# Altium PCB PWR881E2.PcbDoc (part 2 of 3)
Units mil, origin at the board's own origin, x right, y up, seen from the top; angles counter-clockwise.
Board outline 6500 x 3500 mil, 6 copper layers (Top Layer, Signal Layer 1, Signal Layer 2, Signal Layer 3, Signal Layer 4, Bottom Layer), stack 32.4 mil thick; 330 components, 152 nets, 836 pads, 570 vias.
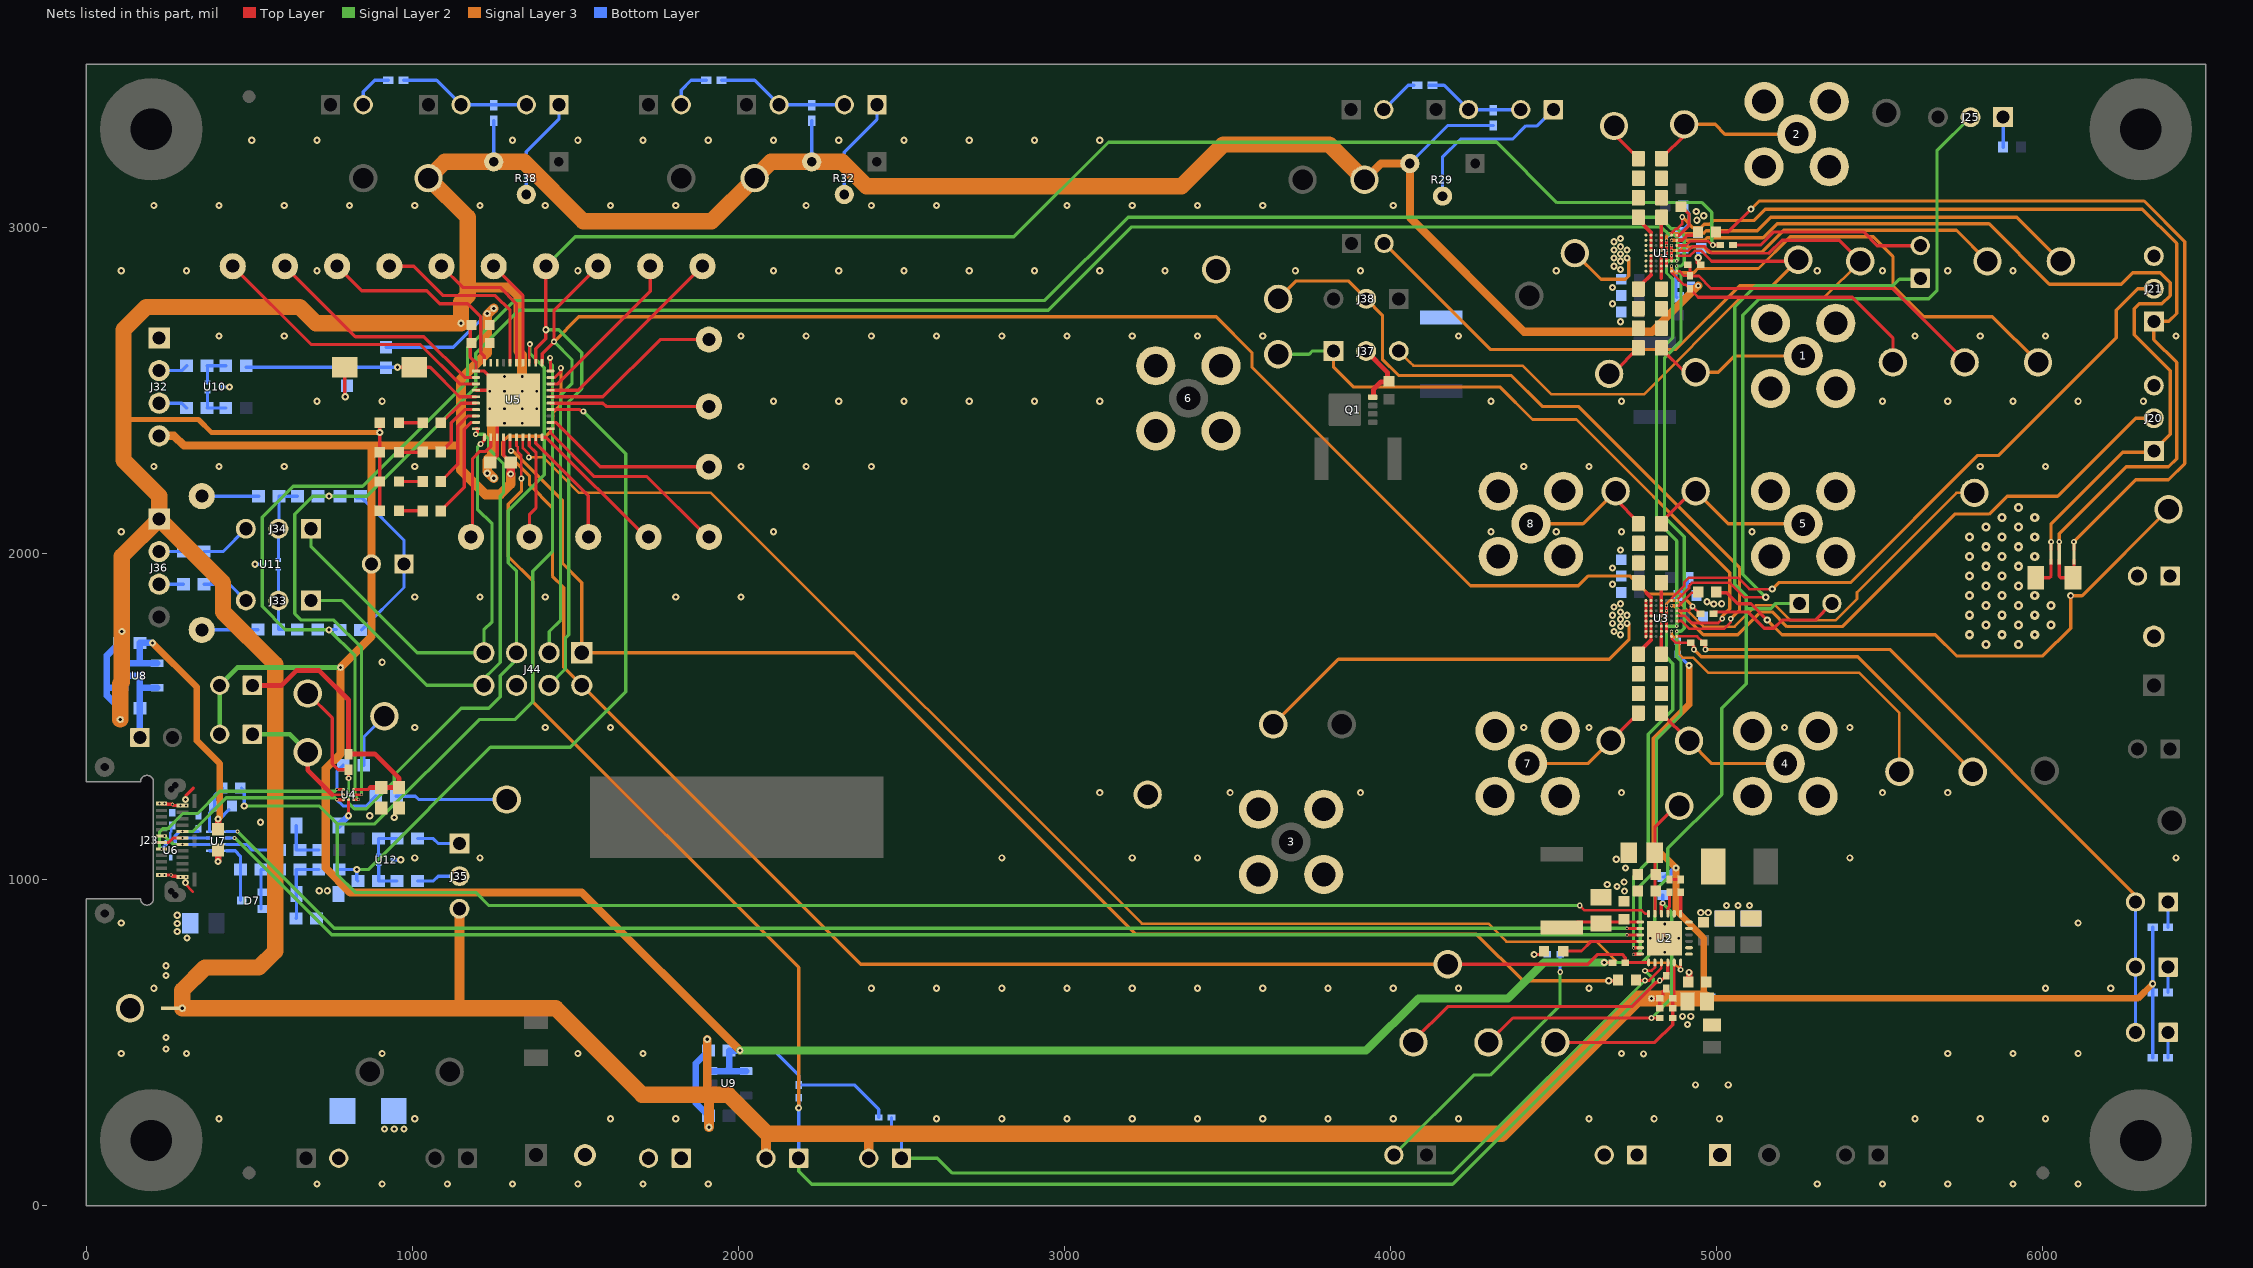
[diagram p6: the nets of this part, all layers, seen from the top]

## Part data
1 2 3 4 5 6 7 8: library part TP_PROBE, "Adaptor, 3.5-mm probe clip (or 131-5031-00)"
C1: "CAP, CERM, 1 µF, 25 V, +/- 10%, X7R, 0805"
C2 C4: "CAP, CERM, 10 µF, 25 V, +/- 20%, X5R, 0603"
C3: "CAP, CERM, 1000 pF, 25 V, +/- 5%, C0G/NP0, 0603"
C5 C29: "CAP, CERM, 1 µF, 25 V, +/- 10%, X5R, 0603"
C6 C28: "CAP, CERM, 0.22 µF, 16 V, +/- 10%, X7R, 0402"
C7 C30 C45 C57 C58: "CAP, CERM, 10 µF, 10 V, +/- 20%, X7T, 0603"
C8 C31: "CAP, CERM, 4.7 µF, 10 V, +/- 20%, X5R, 0402"
C9: "CAP, CERM, 22 µF, 25 V, +/- 20%, X5R, 0805"
C10 C18 C22 C25 C26: "CAP, CERM, 10 µF, 10 V, +/- 10%, X7R, 0805"
C11: "CAP, CERM, 0.047 µF, 25 V, +/- 10%, X7R, 0402"
C12: "CAP, CERM, 1 µF, 16 V, +/- 10%, X7R, 0603"
C13 C14 C16 C17 C20 C21 C23 C24 C33 C34 C36 C37 C38 C39 C40 C41: "CAP, CERM, 20 µF, 16 V, +/- 20%, X5R, 0704"
C15 C35 C53 C54 C55 C56: "CAP, CERM, 22 µF, 10 V, +/- 20%, X5R, 0603"
C19 C51 C52: "CAP, CERM, 4.7 µF, 16 V, +/- 10%, X5R, 0603"
C27 C42 C43 C44 C46 C47: "CAP, CERM, 0.1 µF, 25 V, +/- 10%, X7R, 0603"
C32: "CAP, CERM, 10 µF, 25 V, +/- 10%, X5R, 0805"
C48: "CAP, CERM, 1000 pF, 25 V, +/- 10%, X7R, 0603"
C49 C50: "CAP, CERM, 1 µF, 25 V, +/- 10%, X7R, 0603"
C59 C60: "CAP, CERM, 270 pF, 50 V,+/- 10%, X7R, 0402"
C61: "CAP, CERM, 0.01 µF, 25 V,+/- 10%, X7R, 0603"
D1 D3 D4 D5 D6: "LED, Green, SMD"
D2: "Diode, TVS, Uni, 13 V, SMA"
D7: "Diode, Switching, 75 V, 0.15 A, SOT-323"
D8 D9: "Diode, Zener, 3.6 V, 500 mW, SOD-123"
D10: "Diode, TVS, Uni, 5 V, 19.6 Vc, SOD-323"
FID1 FID2 FID3 FID4 FID5 FID6: "Fiducial mark.  There is nothing to buy or mount."
H1 H3 H5 H7: "Standoff, Hex, 0.5\"L #4-40 Nylon"
H2 H4 H6 H8: "Machine Screw, Round, #4-40 x 1/4, Nylon, Philips panhead"
J1 J6 J8 J9: library part PEC02SAAN, "Header, 100mil, 2x1, Tin, TH"
J2 J3 J4 J7 J10 J12 J13 J14 J15 J16 J17 J18 J19 J22 J24 J26 J27 J29 J30 J31 J39 J40 J41 J42 J43: "Header, 100mil, 2x1, Tin, TH"
J5 J11 J28: "Conn Term Block, 2POS, 3.81mm, TH"
J20 J21 J25 J33 J34 J35 J37 J38: "Header, 2.54 mm, 3x1, Tin, TH"
J23: "Connector, Receptacle, USB Type C, R/A, SMT"
J32 J36: "Header (friction lock), 100mil, 4x1, R/A, TH"
J44: "Header(shrouded), 2.54mm, 4x2, Gold, TH"
L1: "Inductor, Shielded Drum Core, Powdered Iron, 1 µH, 7 A, 0.0181 ohm, SMD"
LBL1: library part THT-14-423-10, "Thermal Transfer Printable Labels, 0.650\" W x 0.200\" H - 10,000 per roll"
Logo1: library part TI_Logo, "Texas Instrument Corporate Signature"
Logo2: library part Pb-Free
Logo3: library part FCC_disclaimer, "FCC_disclaimer"
NT1 NT2 NT3 NT4 NT5 NT6 NT7: "Single point connection between nets."
Q1: "MOSFET, N-CH, 30 V, 60 A, DQG0008A (VSON-CLIP-8)"
R1 R4 R6 R7 R8 R19 R26 R27 R28 R30 R31 R34 R37: "RES, 10 k, 5%, 0.063 W, 0402"
R2: "RES, 2.21 k, 1%, 0.063 W, 0402"
R3: "RES, 18 k, 5%, 0.063 W, 0402"
R5 R10 R65 R66 R69 R70: "RES, 1.00 k, 1%, 0.1 W, 0603"
R9: "RES, 130, 1%, 0.063 W, 0402"
R11 R12 R20 R24: "RES, 0, 5%, 1.5 W, AEC-Q200 Grade 0, 2512"
R13: "RES, 0, 5%, 0.063 W, 0402"
R14: "RES, 0, 1%, 0.5 W, 0805"
R15 R16 R33 R35: "RES, 100, 5%, 0.1 W, 0603"
R17: "RES, 30.1 k, 1%, 0.063 W, 0402"
R18: "RES, 5.23 k, 1%, 0.063 W, 0402"
R21: "RES, 180 k, 5%, 0.063 W, 0402"
R22: "RES, 75 k, 5%, 0.063 W, 0402"
R23: "RES, 39 k, 5%, 0.063 W, 0402"
R25: "RES, 0.01, 1%, 1 W, 1206"
R29 R32 R38: "Trimmer, 100k ohm, 0.25W, TH"
R36: "RES, 0.002, 1%, 1 W, 1206"
R39 R40 R41 R42: "RES, 2.20 k, 1%, 0.1 W, 0603"
R43: "RES, 200 k, 5%, 0.063 W, 0402"
R44 R48 R49 R50 R51 R55 R56 R59 R60 R61 R62 R63 R64 R67 R68: "RES, 100, 1%, 0.1 W, 0603"
R45 R52: "RES, 10.0 k, 1%, 0.1 W, 0603"
R46: "RES, 47.0 k, 1%, 0.1 W, 0603"
R47: "RES, 0, 5%, 0.1 W, 0603"
R53 R54: "RES, 499, 0.5%, 0.1 W, 0603"
R57 R58: "RES, 4.70 k, 1%, 0.1 W, 0603"
S1: "Switch, SPST-NO, Off-Mom, 0.05 A, 12 V, SMT"
SH-J1 SH-J6 SH-J9 SH-J16 SH-J17 SH-J18 SH-J19 SH-J20p SH-J20s SH-J21p SH-J21s SH-J22 SH-J24 SH-J26 SH-J30 SH-J31 SH-J37p SH-J37s SH-J38p SH-J38s SH-J39 SH-J40 SH-J41 SH-J42 SH-J43: "Shunt, 100mil, Gold plated, Black"
TP1 TP2 TP3 TP4 TP5 TP6 TP7 TP8 TP9 TP10 TP11 TP12 TP13 TP14 TP15 TP16 TP17 TP18 TP19 TP20 TP21 TP22 TP23 TP24 TP25 TP26 TP27 TP28 TP29 TP30 TP31 TP32 TP33 TP34 TP35 TP36 TP37 TP38 TP39 TP40 TP41 TP42 TP43 TP44 TP45 TP46 TP49 TP66 TP67 TP68: library part 5012, "Test Point, Multipurpose, White, TH"
TP47 TP48 TP50 TP51 TP52 TP53 TP54 TP55 TP56 TP57 TP58 TP59 TP60 TP61 TP62 TP63 TP65: library part 5002, "Test Point, Miniature, White, TH"
TP64: library part 5004, "Test Point, Miniature, Yellow, TH"
U1 U3: library part CMP-0075378-1, "97% Efficient, 8A Switched Cap Battery Charger with Integrated Protection, I2C Programmability and ADC, YFF0056ACAJ (DSBGA-56)"
U2: "I2C Controlled 5A Single Cell Charger with NVDC Power Path Management and MaxChargeTM High Voltage Adapter Support, RTW0024H (WQFN-24)"
U4: "USB Type-C Port Control with Power Delivery, YFF0009AJAK (DSBGA-9)"
U5: "MIXED SIGNAL MICROCONTROLLER, RHA0040B (VQFN-40)"
U6: "ESD Solution for Super-Speed (6 Gbps) USB 3.0 Interface, 2 Channels, -40 to +85 degC, 3-pin SOT (DRT), Green (Rohs & No Sb/Br)"
U7: "High-Speed USB 2.0 (480 Mbps) 1:2 Multiplexer / Demultiplexer Switch with Single Enable, 6 ohm RON, 2.5 to 3.3V, -40 to 85 degC, 10-Pin UQFN (RSE), Green (RoHS & no Sb/Br)"
U8 U9: "Single Output LDO, 150 mA, Fixed 3.3 V Output, 2.5 to 24 V Input, with Ultra-Low IQ, 5-pin SOT-23 (DBV), -40 to 125 degC, Green (RoHS & no Sb/Br)"
U10 U11 U12: "ESD / Surge Solution for High Speed, Low Voltage Interface, 2 Channels, -40 to +85 degC, 3-pin SOT (DRT), Green (RoHS & no Sb/Br)"
ZZ1: library part AssemblyNoteLabel
ZZ2 ZZ3 ZZ4: library part AssemblyNote

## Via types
v1: diameter 22, hole 10, Top Layer to Bottom Layer, tented both sides, 399 vias
v2: diameter 10, hole 6, Top Layer to Bottom Layer, tented both sides, 72 vias
v3: diameter 18, hole 8, Top Layer to Bottom Layer, tented both sides, 37 vias
v4: diameter 28, hole 12, Top Layer to Bottom Layer, tented both sides, 36 vias
v5: diameter 19.68, hole 7.87, Top Layer to Bottom Layer, 23 vias
v6: diameter 12, hole 6, Top Layer to Bottom Layer, tented both sides, 2 vias
v7: diameter 19.68, hole 7.87, Top Layer to Bottom Layer, tented both sides, 1 vias

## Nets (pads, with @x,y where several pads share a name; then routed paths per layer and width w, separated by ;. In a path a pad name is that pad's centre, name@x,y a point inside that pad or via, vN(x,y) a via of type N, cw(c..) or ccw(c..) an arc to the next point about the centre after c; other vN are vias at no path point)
3V3_C: C47.2 C51.1 R45.1 U7.10 U8.3 U8.4 | length 934.3
  Top Layer w20: C47.2@405,1153.5 v1(405,1185)
  Signal Layer 3 w20: v1(204,1725) 340,1589 340,1425 410,1355 410,1190 v1(405,1185)
  Bottom Layer w10: U7.10@405,1152.43 v1(405,1185) ; v1@410,1185 R45.1@438.25,1213.25
  Bottom Layer w20: U8.3@109.87,1662.4 U8.4@218.13,1662.4 ; 165.5,1668.9 C51.1@165.5,1725 v1(204,1725)
3V3_SYS: C42.1 C43.1 C44.1 C52.1 J30.2 J31.2 J32.4 J41.2 J42.1 J43.1 R4.2 R6.2 R7.2 R46.2 U5.14 U5.38 U5.39 U9.3 U9.4 | length 12165
  Top Layer w10: U5.14@1280.47,2355.83 1280.47,2300.02 C42.1@1302.5,2278 ; v1(4655,745) R6.2@4680.31,745
  Top Layer w25: v1@1302.5,2242.5 C42.1@1302.5,2278
  Signal Layer 2 w10: v1(4655,745) 4770,745 4818,793 4818,842 4810,850 4810,965 4850,1005 4850,1095 5015,1260 5015,1525 5090,1600 5090,1870 5055,1905 5055,2755 5120,2820 5540,2820 5560,2840 J43.1@5625,2840 ; 5090,1830 5165,1830 5181,1846 J42.1@5253,1846
  Signal Layer 2 w15: J30.2@410,1445 J31.2@410,1595 465,1650 v1(780,1650)
  Signal Layer 2 w25: v1(2005,475) 3925,475 4085,635 4360,635 4470,745 v1(4655,745)
  Signal Layer 3 w25: J32.4@224.41,2360 270,2360 300,2330 875,2330 ; 1150,2330 875,2330 ; v1(2005,475) 1520,960 810,960 735,1035 735,1340 780,1385 v1(780,1650) 875,1745 875,2330
  Signal Layer 3 w30: v1(1250,2750) 1230,2730 1230,2614 1150,2534 1150,2330 1150,2255 1225,2180 1270,2180 1302,2212 v1(1302,2243)
  Bottom Layer w10: R46.2@920,2631.5 1126.5,2631.5 v1(1230,2735) ; v1(2005,475) 2110,475 2185,400 R4.2@2185,369.69 2355.31,369.69 2430.31,294.69 R7.2@2430.31,270
  Bottom Layer w20: U9.3@1915.87,412.4 1965,412.4 ; v1(2005,475) C52.1@1971.5,475 1971.5,418.9 1965,412.4 ; U9.4@2024.13,412.4 1965,412.4
\RST_MCU: C48.1 R46.1 R51.1 S1.2 U5.5 | length 741.7
  Top Layer w10: v1(955,2570) 1055,2570 1145.16,2479.84 U5.5@1195.83,2479.84
  Bottom Layer w10: R51.1@491.5,2570 v1(955,2570)
AGND: C8.2 C19.2 C31.2 C42.2 C43.2 C44.2 C49.2 C50.2 C51.2 C52.2 D3.2 D4.2 D5.2 D6.2 J2.2 J3.2 J35.3 J36.1 NT1.2 R8.1 R9.2 R17.1 R19.1 R21.1 R22.1 R23.1 R27.1 R29.3 R30.1 R32.3 R34.1 R38.3 TP32.1 TP34.1 TP45.1 U5.1 U5.4 U5.13 U5.41@1310,2470 U8.1 U9.1 | length 21825.1
  Top Layer w10: D6.2@900.47,2130 D5.2@900.47,2220 D4.2@900.47,2310 v1(900.47,2370) D3.2@900.47,2400 ; C44.2@1178.5,2700 1178.5,2601.5 1195.83,2584.17 U5.1@1195.83,2558.58 1221.42,2558.58 U5.41@1280.47,2499.53 ; U5.4@1195.83,2499.53 U5.41@1280.47,2499.53 ; C42.2@1239.5,2278 1260.79,2299.28 U5.13@1260.79,2355.83 1260.79,2420.79 v5(1283.03,2443.03) U5.41@1310,2470 v5(1283.03,2496.97) U5.41@1280.47,2499.53 ; v1(4800,635) R19.1@4820.31,635 ; R17.1@4820.31,610 R17.1@4825.31,605 R19.1@4825.31,635 4825.31,635.32 4835,645 4835,655.31 R9.2@4845,665.31
  Signal Layer 3 w15: 115,2405 120,2410 345,2410 385,2370 v1(900.47,2370)
  Signal Layer 3 w20: v1(4915,1656) 4915,1536 4810,1431 4810,1100 v1(4875,1035) 4875,905 4960,820 4960,635 6291.38,635 v1(6336.38,680)
  Signal Layer 3 w25: 1905,340 v1(1905,510) ; TP32.1@3920,3145 3970,3195 R29.3@4059,3195 4059,3029 4409,2679 4802,2679 v3(4943,2820)
  Signal Layer 3 w30: 1144,605 1145,606 J35.3@1145,910 ; 1170,2815 1300,2815 1325,2790 1325,2620 1336.97,2608.03 v5(1336.97,2541.85) ; 1245,2400 1245,2300 1230,2285 1230,2250 v1(1250,2230) ; v1(1910,240) 1910,340 ; J2.2@2085,145 2085,216 ; J3.2@2400,145 2400,220
  Signal Layer 3 w50: v1(105,1490) 105,1600 110,1605 110,1990.59 J36.1@224.41,2105 ; TP32.1@3920,3145 3812,3253 3487,3253 3359,3125 2393,3125 2318,3200 R32.3@2225,3200 2100,3200 TP34.1@2050,3150 1918,3018 1525,3018 1343,3200 R38.3@1250,3200 1100,3200 TP45.1@1050,3150 1170,3030 1170,2790 1150,2770 v1(1150,2705) 705,2705 655,2755 185,2755 115,2685 115,2405 115,2285 224.41,2175.59 J36.1@224.41,2105 ; 4960,635 4755,635 4340,220 2400,220 2089,220 1969,340 1910,340 1705,340 1440,605 1144,605 v1(295,605) 295,660 365,730 530,730 580,780 580,1660 420,1820 420,1909.41 J36.1@224.41,2105
  Bottom Layer w10: R38.3@1250,3200 R34.1@1250,3326.38 ; R32.3@2225,3200 R30.1@2225,3326.38 ; J3.2@2400,145 2400,199.68 R8.1@2430.32,230 ; R29.3@4059,3195 4175.38,3311.38 R27.1@4315,3311.38 ; C19.2@4835,1007.56 C19.2@4847.56,1007.56 ; C31.2@4880,1690.31 v1@4914.31,1656 ; C8.2@4915.69,2820 v3(4943,2820) v3@4945,2820 ; R21.1@6336.38,453 R22.1@6336.38,653 v1(6336.38,680) R23.1@6336.38,853
  Bottom Layer w20: v1(105,1490) 105,1522.5 64,1563.5 64,1590 ; U8.1@109.87,1587.6 66.4,1587.6 64,1590 ; v1(110,1760) 110,1732.5 C51.2@102.5,1725 64,1686.5 64,1590 ; v1(1905,510) 1905,471.5 1870,436.5 1870,340 ; v1(1910,240) 1910,273.5 C50.2@1908.5,275 1870,313.5 1870,340 ; U9.1@1915.87,337.6 1872.4,337.6 1870,340 ; C19.2@4847.56,1007.56 v1(4875,1035)
  other v1: 1230,2245
  other v5: 1283.03,2398.15 1336.97,2398.15 1238.15,2443.03 1336.97,2443.03 1381.85,2443.03 1238.15,2496.97 1336.97,2496.97 1381.85,2496.97 1283.03,2541.85
BATN: NT7.2 R16.2 | length 2675.5
  Top Layer w10: R16.2@4995,2985 5035,2985 v1(5105,3055) ; NT7.2@6095,2010 v3(6095,2035)
  Signal Layer 3 w10: v1(5105,3055) 5130,3080 6310,3080 6435,2955 6435,2275 6385,2225 6285,2225 v3(6095,2035)
CC1_SCH: C60.1 J23.A5 R70.2 U4.C1 U6.2 | length 770.5
  Top Layer w10: v2(769.25,1244.25) U4.C1@789.25,1244.25
  Signal Layer 2 w10: v2(296.26,1146.57) 326.58,1146.57 430,1250 763.5,1250 v2(769.25,1244.25)
  Bottom Layer w10: U6.2@273.78,1117.64 273.78,1133.78 286.58,1146.57 C60.1@345,1146.57 ; v2(769.25,1244.25) 788.5,1225 858.5,1225 R70.2@888.5,1255
CC2_SCH: C59.1 J23.B5 R69.2 U4.A1 U6.1 | length 836.4
  Top Layer w10: v2(769.25,1275.75) U4.A1@789.25,1275.75
  Signal Layer 2 w10: v2(231.3,1093.43) 225,1099.72 225,1145 235,1155 250,1155 297,1202 342,1202 410,1270 763.5,1270 v2(769.25,1275.75)
  Bottom Layer w7.8: U6.1@246.22,1112.64 258,1124.42 258,1143 262,1147 262,1162.32 C59.1@265,1165.32
  Bottom Layer w10: v2(231.3,1093.43) U6.1@246.22,1108.35 ; v2(769.25,1275.75) 769.25,1330.75 R69.2@788.5,1350
CDRVL_ADDRMS_S: C28.2 J6.2 J8.2 J9.2 U3.H7 | length 2143.9
  Top Layer w8: U3.H7@4877.24,1744.88 4940.12,1744.88 4957.5,1727.5 C28.2@4962.5,1727.5
  Top Layer w10: C28.2@4959.69,1725 4965,1719.69 v3(4965,1705)
  Signal Layer 3 w10: v3(4965,1705) 5530,1705 J9.2@6279,956 ; J9.2@6279,931 J9.2@6284,931
  Bottom Layer w10: J6.2@6284,531 J8.2@6284,731 J9.2@6284,931
CE_SCHG: J44.1 R10.1 U5.15 | length 4350
  Top Layer w8: v3@1300.16,2316.84 U5.15@1300.16,2355.83
  Top Layer w10: v3@1300.16,2316.84 v3(1303,2314) ; v1(4669,689) 4696.44,689 R10.1@4697.44,690
  Signal Layer 3 w10: v3(1303,2314) 1309,2314 1460,2163 1460,1970 1520,1910 J44.1@1520,1695 2356,1695 3219,832 4263,832 4406,689 v1(4669,689)
DN_C: J23.A7 J23.B7 U7.7 | length 147.7
  Signal Layer 2 w10: v2(241.3,1132.8) 266.89,1107.2 v2(296.26,1107.2)
  Bottom Layer w10: v2(296.26,1107.2) U7.7@378.43,1107.16
DN_SCHG: U2.3 U7.2 | length 4456.7
  Top Layer w10: v2@4725,829.84 U2.3@4765.2,829.84
  Signal Layer 2 w10: v6(455,1127) 456.24,1127 753.24,830 4716.72,830 v2(4725,830)
  Bottom Layer w10: U7.2@431.57,1126.84 431.73,1127 v6(455,1127)
DP_C: J23.A6 J23.B6 U7.8 | length 152.8
  Top Layer w10: J23.B6@231.3,1113.11 253.11,1113.11 266.89,1126.89 v2(296.26,1126.89)
  Bottom Layer w10: v2(296.26,1126.89) U7.8@378.43,1126.89
DP_SCHG: U2.2 U7.1 | length 4456.4
  Top Layer w10: v2@4725,849.53 U2.2@4765.2,849.53
  Signal Layer 2 w10: v6(465,1146.53) 761.53,850 v2(4725,850)
  Bottom Layer w10: U7.1@431.57,1146.53 v6(465,1146.53)
DSEL_SCHG: R44.2 U2.24 U5.30 | length 6470.6
  Top Layer w8: v3(4580,920) 4595,905 4770,905 4780.2,894.8 U2.24@4790.79,894.8
  Top Layer w10: U5.30@1424.17,2558.58 v3@1424.17,2600.17
  Signal Layer 2 w10: v1(485,1225) 715,1225 770,1170 ; v3(1423,2599) 1423,2583 1430,2576 1430,2005 1370,1945 1370,1545 1315,1490 1206,1490 886,1170 770,1170 ; v3(4580,920) 1235,920 1195,960 825,960 770,1015 770,1170
  Bottom Layer w10: R44.2@476.5,1280 485,1271.5 v1(485,1225)
GND: 1.2 1.3 1.4 1.5 2.2 2.3 2.4 2.5 3.2 3.3 3.4 3.5 4.2 4.3 4.4 4.5 5.2 5.3 5.4 5.5 6.2 6.3 6.4 6.5 7.2 7.3 7.4 7.5 8.2 8.3 8.4 8.5 C1.2 C2.2 C3.2 C4.2 C5.1 C7.2 C9.2 C10.2 C12.2 C15.2 C18.2 C22.2 C25.2 C26.2 C27.2 C29.1 C30.2 C32.2 C35.2 C45.2 C46.2 C47.1 C48.2 C53.2 C54.2 C55.2 C56.2 C59.2 C60.2 D2.2 D8.2 D9.2 D10.2 J5.1 J7.1 J7.2 J11.2 J12.1 J12.2 J20.3 J21.3 J23.A1 J23.A12 J23.B1 J23.B12 J32.1 J44.6 NT1.1 NT6.1 R3.2 R36.1 R52.1 S1.1 TP16.1 TP17.1 TP18.1 TP36.1 TP37.1 U1.A1 U1.B1 U1.C1 U1.D1 U1.E1 U1.F1 U1.G1 U1.H1 U2.17 U2.18 U2.25 U3.A1 U3.B1 U3.C1 U3.D1 U3.E1 U3.F1 U3.G1 U3.H1 U4.C2 U6.3 U7.5 U7.6 U10.3 U11.3 U12.3 | length 2387.3
  Top Layer w7.8: v1@301.35,988.27 327.81,961.81
  Top Layer w10: J23.B1@231.3,1013.7 v2(261.3,1013.7) 265,1010 275,1010 277.2,1007.8 J23.A12@296.26,1007.8 ; J23.B12@231.3,1232.2 247.8,1232.2 250,1230 v2(265,1230) 268.7,1226.3 J23.A1@296.26,1226.3 ; v1@305,987.75 v1(305,990) ; 307,1258 329,1280 ; S1.1@793.7,2570 793.7,2481.3 v1(795,2480) ; v1(805,1195) U4.C2@805,1244.25 ; U3.H1@4782.76,1742.76 U3.G1@4782.76,1760.63 U3.F1@4782.76,1776.38 U3.E1@4782.76,1792.13 U3.D1@4782.76,1807.87 U3.C1@4782.76,1823.62 U3.B1@4782.76,1839.37 U3.A1@4782.76,1855.12 ; C12.2@4912.44,685 C12.2@4915,687.56 ; R3.2@4943,2891.69 R3.2@4950.69,2884 ; R36.1@5977.91,1925 6020,1925 6025,1930 NT6.1@6025,1980
  Top Layer w15: R3.2@4943,2891.69 v1(4943,2906)
  Top Layer w20: v1(405,1055) C47.1@405,1090.5 ; C12.2@4915,687.56 v1(4915,715)
  Signal Layer 3 w10: TP36.1@3640,1475 3840,1675 4670,1675 4731,1736 4731,1779 v1(4725,1785) ; TP17.1@4565,2920 4645,2840 4720,2840 4730,2850 4730,2900 v1(4725,2905)
  Bottom Layer w10: U7.6@378.43,1087.47 U7.5@405,1087.47 ; v1(405,1055) U7.5@405,1081.57 ; U10.3@417.64,2510 v1(440,2510) ; v1(518,1966) U11.3@544.36,1966 ; v1(795,2480) C48.2@795,2518.5 ; v1@804.47,1195 v1(805,1195) ; U12.3@942.64,1060 v1(965,1060) ; C7.2@4940,2982.56 C7.2@4942.56,2980 ; v1(4943,2906) C5.1@4943,2925.44
  Bottom Layer w20: D9.2@774.47,1165 v1@804.47,1195
  other v1: 708,66 908,66 1108,66 1308,66 1508,66 1708,66 1908,66 5308,66 5508,66 5708,66 5908,66 6108,66 915,235 945,235 975,235 408,266 1008,266 1608,266 1808,266 2608,266 2808,266 3008,266 3208,266 3408,266 3608,266 3808,266 4008,266 4208,266 4608,266 4808,266 5008,266 5608,266 5808,266 6008,266 4935,370 5035,370 4775,465 108,466 308,466 908,466 1508,466 1708,466 4708,466 5708,466 5908,466 6108,466 245,480 245,515 4910,555 4895,580 4920,580 208,666 2408,666 2608,666 2808,666 3008,666 3208,666 3408,666 3608,666 3808,666 4008,666 4208,666 4608,666 6008,666 6208,666 245,705 245,735 310,820 280,840 280,865 108,866 6108,866 280,890 4951,898 4974,898 5030,920 5065,920 5100,920 4717,964 715,965 740,965 4694,978 4664,984 4716,992 4720,1035 4692,1062 1008,1066 1208,1066 2808,1066 3208,1066 3408,1066 5408,1066 6408,1066 535,1175 945,1190 870,1195 305,1245 3108,1266 3508,1266 3908,1266 4708,1266 5508,1266 5708,1266 1008,1466 1408,1466 1608,1466 4408,1466 4608,1466 5208,1466 5408,1466 908,1666 4705,1750 4685,1760 4705,1775 4680,1785 4705,1797.5 4680,1810 4725,1810 4705,1820 4685,1835 4991,1844 4705,1845 5015,1845 4970,1851 1008,1866 1208,1866 1408,1866 1808,1866 2008,1866 4680,1905 4680,1955 4705,2010 108,2066 2108,2066 4308,2066 4508,2066 4708,2066 5108,2066 208,2266 408,2266 608,2266 1008,2266 2008,2266 2208,2266 2408,2266 4408,2266 4608,2266 5808,2266 6008,2266 708,2466 908,2466 2108,2466 2308,2466 2508,2466 2708,2466 2908,2466 3108,2466 4308,2466 4708,2466 5508,2466 5708,2466 5908,2466 6108,2466 6308,2466 408,2666 608,2666 2008,2666 2208,2666 2408,2666 2608,2666 2808,2666 3008,2666 3208,2666 3408,2666 3608,2666 4208,2666 5608,2666 5808,2666 6008,2666 6408,2666 4705,2710 4680,2765 4680,2815 108,2866 308,2866 708,2866 1508,2866 2108,2866 2308,2866 2508,2866 2708,2866 2908,2866 3108,2866 3308,2866 3708,2866 3908,2866 4508,2866 5308,2866 5508,2866 5708,2866 5908,2866 4705,2870 4685,2880 4705,2895 4685,2905 4705,2917.5 4685,2930 4725,2930 4705,2940 4685,2955 4705,2965 4939,3021 4960,3035 4937,3048 208,3066 408,3066 608,3066 808,3066 1008,3066 1208,3066 1408,3066 1608,3066 1808,3066 2208,3066 2408,3066 2608,3066 3008,3066 3208,3066 3408,3066 3608,3066 4008,3066 508,3266 708,3266 1308,3266 1508,3266 1708,3266 1908,3266 2108,3266 2308,3266 2508,3266 2708,3266 2908,3266 3108,3266
  other v2: 290,1007.8 306.26,1007.8 225.04,1013.7 241.3,1013.7 290,1226.3 306.26,1226.3 225.04,1232.2 241.3,1232.2
  other v4: 5825,1720 5925,1720 5775,1750 5875,1750 5975,1750 5825,1780 5925,1780 6025,1780 5775,1810 5875,1810 5975,1810 5825,1840 5925,1840 6025,1840 5775,1870 5875,1870 5975,1870 5825,1900 5925,1900 5775,1930 5875,1930 5825,1960 5925,1960 5775,1990 5875,1990 5975,1990 5825,2020 5925,2020 5775,2050 5875,2050 5975,2050 5825,2080 5925,2080 5875,2110 5975,2110 5925,2140
  other v5: 4840,776.69 4796.69,820 4840,820 4883.31,820 4840,863.31
INT_M: J44.4 R1.1 TP1.1 U1.C7 U5.32 | length 5574.6
  Top Layer w8: U1.C7@4877.24,2943.62 4905.62,2943.62 4918,2956 4974,2956 4985,2945 R1.1@5010.31,2945
  Top Layer w10: U5.32@1378.9,2584.17 1378.9,2626.9 1410,2658 v1(1410,2685) TP1.1@1410,2880
  Signal Layer 2 w10: v1(1410,2685) 1450,2685 1520,2615 1520,2505 1480,2465 1480,1750 1470,1740 1470,1645 J44.4@1420,1595 ; TP1.1@1410,2880 1500,2970 2845,2970 3135,3260 4325,3260 4510,3075 4955,3075 4985,3045 4985,2948 v3(4988,2945)
INT_N_SCH: J44.5 R43.1 TP49.1 U4.B2 U5.33 | length 2265.7
  Top Layer w8: U5.33@1359.21,2584.17 1359.21,2639.21 v3(1361,2641)
  Top Layer w10: TP49.1@680,1570 755,1495 755,1355 773.62,1336.38 R43.1@805,1336.38 v3(805,1310)
  Signal Layer 2 w8: 805,1234 v2(805,1260) v3(805,1310)
  Signal Layer 2 w10: 805,1234 823,1216 860,1216 945,1301 945,1320 1150,1525 1235,1525 1270,1560 1270,1625 1320,1675 J44.5@1320,1695 1320,1945 1295,1970 1295,2130 1405,2240 1405,2569 1361,2613 v3(1361,2641)
INT_S: J44.3 R26.1 TP25.1 U3.C7 U5.31 | length 5404.2
  Top Layer w8: U3.C7@4877.24,1823.62 4912.62,1823.62 v3(4926,1837) R26.1@4951.31,1811.68
  Top Layer w10: U5.31@1398.58,2584.17 1398.58,2611.58 1435,2648 v3(1435,2649) 1435,2745 TP25.1@1570,2880
  Signal Layer 2 w10: J44.3@1420,1695 1420,1760 1455,1795 1455,2485 1490,2520 1490,2594 v3(1435,2649)
  Signal Layer 3 w10: v3(1435,2649) 1511,2725 3465,2725 3575,2615 3575,2570 4245,1900 4575,1900 4605,1930 4735,1930 4790,1875 4888,1875 v3(4926,1837)
INT_SCHG: J44.2 R6.1 TP9.1 U2.7 U5.29 | length 4934.3
  Top Layer w10: U5.29@1424.17,2538.9 1437.9,2538.9 1456,2557 v3(1456,2568) ; TP9.1@4175,745 4180,740 4605,740 4635,770 4710,770 4719.69,760.32 R6.1@4719.69,745 4719.88,745.2 U2.7@4790.79,745.2
  Signal Layer 3 w10: v3(1456,2568) 1456,2456 1432,2432 1432,2381 1410,2359 1295,2359 1277,2341 1277,2302 1299,2280 1316,2280 1360,2236 1360,2210 1430,2140 1430,1930 1465,1895 1465,1650 2375,740 TP9.1@4175,740
LED0: R39.2 U5.6 | length 133.2
  Top Layer w10: R39.2@1087.56,2400 1090,2400 1150.16,2460.16 U5.6@1195.83,2460.16
LED1: R40.2 U5.7 | length 196
  Top Layer w10: R40.2@1087.56,2310 1120,2342.44 1120,2400 1160.47,2440.47 U5.7@1195.83,2440.47
LED2: R41.2 U5.8 | length 260.3
  Top Layer w10: R41.2@1087.56,2220 1140,2272.44 1140,2390 1170.79,2420.79 U5.8@1195.83,2420.79
LED3: R42.2 U5.9 | length 324.6
  Top Layer w10: R42.2@1087.56,2130 1160,2202.44 1160,2380 1181.1,2401.1 U5.9@1195.83,2401.1
Net1_1: 1.1 C13.1 C16.1 C20.1 C23.1 TP19.1 U1.E4 U1.F4 U1.G4 U1.H4 | length 568.7
  Top Layer w10: 4830,2842.56 U1.H4@4830,2864.88 U1.G4@4830,2880.63 U1.F4@4830,2896.38 U1.E4@4830,2912.13 ; C23.1@4830.43,2635 4830.43,2627.23 4902.66,2555 TP19.1@4920,2555
  Signal Layer 3 w10: TP19.1@4920,2555 5005,2555 5055,2605 5250,2605 1.1@5265,2590
Net2_1: 2.1 C14.1 C17.1 C21.1 C24.1 TP20.1 U1.A4 U1.B4 U1.C4 U1.D4 | length 590.7
  Top Layer w10: U1.D4@4830,2927.87 U1.C4@4830,2943.62 U1.B4@4830,2959.37 U1.A4@4830,2975.12 C14.1@4830,3030 ; C24.1@4830.43,3215 4834.48,3215 4900,3280.52 TP20.1@4900,3315
  Signal Layer 3 w10: TP20.1@4900,3315 4995,3315 5025,3285 2.1@5245,3285
Net4_1: 4.1 C33.1 C36.1 C38.1 C40.1 TP41.1 U3.E4 U3.F4 U3.G4 U3.H4 | length 516.1
  Top Layer w8: U3.H4@4830,1744.88 U3.G4@4830,1760.63 U3.F4@4830,1776.38 U3.E4@4830,1792.13
  Top Layer w10: 4830,1715 U3.H4@4830,1744.88 ; C40.1@4830.43,1510 4830.43,1509.57 TP41.1@4915,1425
  Signal Layer 3 w10: TP41.1@4915,1425 4985,1355 4.1@5205,1355
Net5_1: 5.1 C34.1 C37.1 C39.1 C41.1 TP42.1 U3.A4 U3.B4 U3.C4 U3.D4 | length 643
  Top Layer w10: U3.D4@4830,1807.87 U3.C4@4830,1823.62 U3.B4@4830,1839.37 ; U3.A4@4830,1855.12 U3.B4@4830,1839.37 ; C37.1@4830,1901 U3.B4@4830,1839.37 ; C34.1@4830.43,2090 4830.43,2095.43 TP42.1@4927.5,2192.5
  Signal Layer 3 w10: TP42.1@4915,2190 TP42.1@4935,2190 5035,2090 5.1@5265,2090
Net7_1: 7.1 C33.2 C36.2 C38.2 C40.2 TP43.1 U3.E2 U3.F2 U3.G2 U3.H2 | length 513.2
  Top Layer w10: TP43.1@4675,1425 4675,1425.43 C40.2@4759.57,1510 ; 4798.5,1733.94 U3.H2@4798.5,1744.88 U3.G2@4798.5,1760.63 U3.F2@4798.5,1776.38 U3.E2@4798.5,1792.13
  Top Layer w12: C33.2@4769.78,1705.22 4798.5,1733.94
  Signal Layer 3 w10: 7.1@4420,1380 4445,1355 4605,1355 TP43.1@4675,1425
Net8_1: 8.1 C34.2 C37.2 C39.2 C41.2 TP44.1 U3.A2 U3.B2 U3.C2 U3.D2 | length 548.8
  Top Layer w10: TP44.1@4690,2190 4690,2165 4759.57,2095.43 C34.2@4759.57,2090 ; U3.D2@4798.5,1807.87 U3.C2@4798.5,1823.62 U3.B2@4798.5,1839.37 ; U3.A2@4798.5,1855.12 U3.B2@4798.5,1839.37 ; 4798.5,1864.5 U3.B2@4798.5,1839.37
  Top Layer w12: 4785,1878 4798.5,1864.5
  Signal Layer 3 w10: 8.1@4430,2090 4590,2090 TP44.1@4690,2190 4695,2195 TP44.1@4715,2195
NetC1_1: C1.1 C3.1 R11.1 U2.1 | length 192.9
  Top Layer w10: R11.1@4572.32,869.21 U2.1@4765.2,869.21
NetC2_1: C2.1 C4.1 C9.1 TP10.1 U2.23 | length 371.1
  Top Layer w10: U2.23@4810.47,894.8 4810.47,1160.47 TP10.1@4885,1235
NetC5_2: C5.2 R12.1 TP7.1 U1.C6 U1.D6 U1.E6 U1.F6 | length 1094.1
  Top Layer w10: U1.F6@4861.5,2896.38 v2(4861.5,2912.13) v2(4861.5,2927.87) v2(4861.5,2943.62)
  Signal Layer 3 w10: v2(4861.5,2927.87) 4887.13,2927.87 4898.25,2939 4960,2939 4976,2923 5138,2923 5205,2990 5735,2990 TP7.1@5830,2895
NetC6_1: C6.1 TP4.1 U1.H6 | length 840.9
  Top Layer w8: U1.H6@4861.5,2864.88 4861.5,2860.5 4899,2823 4905,2823 4943,2785
  Top Layer w10: 4943,2785 5415,2785 5540,2660 TP4.1@5540,2585
NetC6_2: C6.2 R3.1 TP3.1 U1.H7 | length 1035.6
  Top Layer w8: U1.H7@4877.24,2864.88 4885.12,2864.88 4899.31,2850.69 C6.2@4918,2850.69 R3.1@4918,2885 ; C6.2@4918,2850 4945,2850 4983,2812 ; TP3.1@5760,2585 TP3.1@5760,2590
  Top Layer w10: 4983,2812 5538,2812 TP3.1@5760,2590
NetC7_1: C7.1 C57.2 TP5.1 U1.B5 U1.C5 U1.D5 U1.E5 U1.F5 U1.G5 | length 1597
  Top Layer w10: U1.G5@4845.75,2880.63 U1.F5@4845.75,2896.38 v2(4845.75,2912.13) v2(4845.75,2927.87) v2(4845.75,2943.62) v2(4845.75,2959.37)
  Signal Layer 3 w10: v2(4845.75,2959.37) 4845.75,2970.75 4855,2980 4958,2980 4967,2989 5124,2989 5165,3030 5920,3030 TP5.1@6055,2895
  Bottom Layer w10: v2(4845.75,2912.13) v2(4845.75,2927.87) v2(4845.75,2943.62) v2(4845.75,2959.37) 4845.75,2966.75 4859,2980 C7.1@4895,2980 ; C7.1@4887.44,2983 4915,3010.56 4915,3042 C57.2@4888.56,3068.44
NetC8_1: C8.1 R5.1 TP6.1 U1.G6 | length 1499.1
  Signal Layer 3 w10: v2(4861.5,2880.63) 4861.5,2868.5 4870,2860 4929,2860 4942,2873 5128,2873 5225,2970 5480,2970 5540,2910 5540,2820 5635,2725 5845,2725 TP6.1@5985,2585
  Bottom Layer w10: v2(4861.5,2880.63) 4861.5,2871.5 4874.31,2858.69 4874.31,2788.13 R5.1@4877.44,2785
NetC10_1: C10.1 C12.1 R14.1 U2.13 U2.14
NetC11_1: C11.1 R13.1 | length 35
  Top Layer w10: R13.1@4855,999.68 C11.1@4890,999.68
NetC11_2: C11.2 L1.1 U2.19 U2.20 | length 54.4
  Top Layer w10: U2.19@4889.21,894.8 C11.2@4889.21,949.21
NetC13_2: C13.2 C16.2 C20.2 C23.2 TP21.1 U1.E2 U1.F2 U1.G2 U1.H2 | length 224.8
  Top Layer w10: TP21.1@4670,2555 4685,2555 4759.57,2629.57 C23.2@4759.57,2635 ; 4798.5,2853.5 U1.H2@4798.5,2864.88 U1.G2@4798.5,2880.63 U1.F2@4798.5,2896.38 U1.E2@4798.5,2912.13
  Top Layer w12: C13.2@4770,2825 4798.5,2853.5
NetC14_2: C14.2 C17.2 C21.2 C24.2 TP22.1 U1.A2 U1.B2 U1.C2 U1.D2 | length 240.3
  Top Layer w10: TP22.1@4685,3320 4685,3285 4755,3215 C24.2@4759.57,3215 ; U1.D2@4798.5,2927.87 U1.C2@4798.5,2943.62 U1.B2@4798.5,2959.37 U1.A2@4798.5,2975.12 4798.5,2983.94
  Top Layer w12: C14.2@4766.22,3016.22 4798.5,2983.94
NetC19_1: C19.1 R18.1 TP13.1 U2.22 | length 1005.3
  Top Layer w10: TP13.1@4300,500 4375,575 v3(4800,575) R18.1@4825.31,575 ; U2.22@4830.16,894.8 4830.16,923.16 v3(4834,927)
  Signal Layer 2 w10: v3(4800,575) 4862,637 4862,899 v3(4834,927)
  Bottom Layer w10: v3(4834,927) 4834,951.44 C19.1@4835,952.44
NetC28_1: C28.1 TP27.1 U3.H6 | length 1105.1
  Top Layer w8: U3.H6@4861.5,1744.88 4861.5,1738.5 4875,1725 C28.1@4920.31,1725
  Top Layer w10: C28.1@4920.31,1725 4930,1715.32 v3(4930,1705)
  Signal Layer 3 w10: v3(4930,1705) 4952,1683 5432,1683 TP27.1@5785,1330
NetC30_1: C30.1 C58.2 TP28.1 U3.B5 U3.C5 U3.D5 U3.E5 U3.F5 U3.G5 | length 1446.8
  Top Layer w10: U3.G5@4845.75,1760.63 U3.F5@4845.75,1776.38 v2(4845.75,1792.13) v2(4845.75,1807.87) v2(4845.75,1823.62) v2(4845.75,1839.37)
  Signal Layer 3 w8: v2(4845.75,1839.37) 4845.75,1845.75 4855,1855 4879,1855 4959,1775 5055,1775 5120,1840 5180,1840 5225,1795 5365,1795 5430,1860 5430,1880 5735,2185 TP28.1@5790,2185
  Bottom Layer w8: v2(4845.75,1792.13) v2(4845.75,1807.87) v2(4845.75,1823.62) v2(4845.75,1839.37) 4845.75,1845.75 4855,1855 4867.44,1855 C30.1@4882.44,1870
  Bottom Layer w10: C30.1@4882.44,1870 4910,1897.56 C58.2@4910,1919.88
NetC31_1: C31.1 TP29.1 U3.G6 | length 1053.5
  Signal Layer 3 w8: v2(4861.5,1760.63) 4861.5,1751.5 4885,1728 4885,1690 4895,1680 4927,1680 4974,1633 5437,1633 5560,1510 TP29.1@5560,1330
  Bottom Layer w8: v2(4861.5,1760.63) 4861.5,1748.5 4880,1730 C31.1@4880,1724.68
NetC45_1: C45.1 C46.1 J31.1 R43.2 U4.A3 | length 867.1
  Top Layer w8: U4.A3@820.75,1275.75 865.75,1275.75
  Top Layer w10: 865.75,1275.75 871.5,1281.5
  Top Layer w15: J31.1@510,1595 600,1595 645,1640 715,1640 805,1550 805,1385 885,1385 960,1310 960,1290 951.5,1281.5 C46.1@905,1281.5 871.5,1281.5
NetC49_1: C49.1 J40.1 U8.2 U8.5 | length 298.3
  Bottom Layer w20: U8.2@109.87,1625 165,1625 J40.1@165,1435 ; 165,1587.6 U8.5@218.13,1587.6
NetC61_2: C61.2 J37.2 Q1.4 | length 198
  Top Layer w15: J37.2@3925,2620 3990,2555 3990,2525 3970,2525 3947.04,2502.04 Q1.4@3947.04,2478.39
NetD1_1: D1.1 R2.1 | length 70.8
  Top Layer w10: v1(4440,770) D1.1@4470.47,770
  Bottom Layer w10: v1(4440,770) R2.1@4480.31,770
NetD1_2: D1.2 U2.4 | length 248.2
  Top Layer w9: D1.2@4529.53,780 4585,780 4615.16,810.16 U2.4@4765.2,810.16
NetD2_1: D2.1 J17.2
NetD3_1: D3.1 R39.1 | length 72.9
  Top Layer w10: D3.1@959.53,2400 R39.1@1032.44,2400
NetD4_1: D4.1 R40.1 | length 72.9
  Top Layer w10: D4.1@959.53,2310 R40.1@1032.44,2310
NetD5_1: D5.1 R41.1 | length 72.9
  Top Layer w10: D5.1@959.53,2220 R41.1@1032.44,2220
NetD6_1: D6.1 R42.1 | length 72.9
  Top Layer w10: D6.1@959.53,2130 R42.1@1032.44,2130
NetD7_1: D7.1 D7.2 R47.2 R48.1 | length 177.6
  Bottom Layer w10: D7.2@536.5,909.41 R47.2@536.5,1030 R48.1@593.5,1030
NetD7_3: D7.3 R47.1 U7.4 | length 185
  Bottom Layer w10: U7.4@431.57,1087.47 457.53,1087.47 473.5,1071.5 R47.1@473.5,1030 D7.3@473.5,935
NetD8_1: D8.1 R48.2 R52.2 R53.1 | length 219.6
  Bottom Layer w10: R52.2@643.5,880 645.53,882.03 D8.1@645.53,955 645,955.53 645,1030 R48.2@656.5,1030 R53.1@713.5,1030
NetD9_1: D9.1 R49.2 R54.1 | length 143.7
  Bottom Layer w10: D9.1@645.53,1165 645,1164.47 645,1090 R49.2@656.5,1090 R54.1@713.5,1090
NetJ1_2: J1.2 R2.2 | length 856.1
  Signal Layer 2 w10: J1.2@4010,155 4255,400 4305,400 4519.69,614.69 v3@4519.69,716
  Bottom Layer w10: v3@4519.69,715.31 R2.2@4519.69,770
  other v3: 4520,716
NetJ3_1: J3.1 R7.1 R8.2 R10.2 U2.9 | length 2794.5
  Top Layer w8: R10.2@4752.56,690 v3(4780,690) 4792.56,690 4830.16,727.6 U2.9@4830.16,745.2
  Signal Layer 2 w10: J3.1@2500,145 2610,145 2655,100 4190,100 v3(4780,690)
  Bottom Layer w10: R7.1@2469.68,270 R8.2@2469.69,230 2475,230 2500,205 J3.1@2500,145
NetJ6_1: J6.1 R21.2 | length 78.2
  Bottom Layer w10: R21.2@6383.62,453 6383.62,530.62 J6.1@6384,531
NetJ8_1: J8.1 R22.2 | length 78.2
  Bottom Layer w10: R22.2@6383.62,653 6383.62,730.62 J8.1@6384,731
NetJ9_1: J9.1 R23.2 | length 78.2
  Bottom Layer w10: R23.2@6383.62,853 6383.62,930.62 J9.1@6384,931
NetJ13_2: J13.2 J15.2 R27.2 R28.1 | length 311.4
  Bottom Layer w10: R28.1@4118.62,3435 4164,3435 J13.2@4239,3360 J15.2@4399,3360
NetJ14_2: J14.2 R28.2 | length 123.4
  Bottom Layer w10: J14.2@3979,3360 4054,3435 R28.2@4071.38,3435
NetJ15_1: J15.1 R29.2 | length 519.5
  Bottom Layer w10: R29.2@4159,3095 4159,3214 4215,3270 4375,3270 4415,3310 4449,3310 J15.1@4499,3360
NetJ16_2: J16.2 J19.2 R30.2 R31.1 | length 407.4
  Bottom Layer w10: R31.1@1948.62,3450 2050,3450 J16.2@2125,3375 J19.2@2325,3375
NetJ18_2: J18.2 R31.2 | length 133.8
  Bottom Layer w10: J18.2@1825,3375 1825,3420 1855,3450 R31.2@1901.38,3450
NetJ19_1: J19.1 R32.2 | length 316.4
  Bottom Layer w10: R32.2@2325,3100 2325,3229.63 2425,3329.63 J19.1@2425,3375
NetJ20_2: J20.2 U3.B6 | length 1842.8
  Signal Layer 3 w10: v2(4861.5,1839.37) 4869.63,1839.37 4959,1750 5065,1750 5135,1820 5170,1820 5215,1775 5385,1775 5730,2120 5835,2120 5890,2175 6045,2175 6284,2414 J20.2@6355,2414
NetJ21_2: J21.2 U3.A6 | length 1962.8
  Top Layer w8: U3.A6@4861.5,1855.12 4861.5,1861.5 4900,1900 4900,1910 4915,1925 5065,1925 5100,1890 v1(5170,1890)
  Signal Layer 3 w10: v1(5170,1890) 5190,1910 5410,1910 5800,2300 5865,2300 6225,2660 6225,2745 6291,2811 J21.2@6340,2811
NetJ22_2: J22.2 J26.2 R34.2 R37.1 | length 407.4
  Bottom Layer w10: R37.1@973.62,3450 1075,3450 J22.2@1150,3375 J26.2@1350,3375
NetJ24_2: J24.2 R37.2 | length 130.9
  Bottom Layer w10: J24.2@850,3375 850,3415 885,3450 R37.2@926.38,3450
NetJ25_1: J25.1 R35.2 | length 92
  Bottom Layer w10: R35.2@5878,3245 J25.1@5878,3337
NetJ25_2: J25.2 U3.A7 | length 2412.2
  Top Layer w8: U3.A7@4877.24,1855.12 4915,1892.87 4915,1900 4924,1909 5041,1909 5085,1865 v1(5150,1865)
  Signal Layer 2 w10: v1(5150,1865) 5080,1935 5080,2730 5130,2780 5650,2780 5675,2805 5675,3234 J25.2@5778,3337
NetJ26_1: J26.1 R38.2 | length 316.4
  Bottom Layer w10: R38.2@1350,3100 1350,3230.63 1450,3330.63 J26.1@1450,3375
NetJ28_2: J28.2 J29.1 J29.2 NT5.1 NT7.1 R33.2 R36.2 TP39.1 | length 1864.1
  Top Layer w10: R33.2@4996.56,1879 5031,1879 5065,1845 5105,1845 v1(5155,1795) ; NT5.1@6050,1980 6050,1930 6055,1925 R36.2@6092.09,1925 6095,1927.91 NT7.1@6095,1980
  Signal Layer 3 w10: v1(5155,1795) 5200,1750 5670,1750 5735,1685 6000,1685 6085,1770 v1(6085,1870) 6120,1870 TP39.1@6385,2135
NetJ30_1: J30.1 TP46.1 U4.B1 | length 383.1
  Top Layer w8: 755,1260 U4.B1@789.25,1260
  Top Layer w15: TP46.1@680,1390 680,1335 755,1260
  Signal Layer 2 w15: J30.1@515,1445 625,1445 TP46.1@680,1390
NetJ32_2: J32.2 R56.2 | length 90.3
  Bottom Layer w10: J32.2@224.41,2560 293.5,2560 R56.2@308.5,2575
NetJ32_3: J32.3 R55.2 | length 90.3
  Bottom Layer w10: J32.3@224.41,2460 293.5,2460 R55.2@308.5,2445
NetJ33_2: J33.2 R59.2 R65.1 U11.2 | length 239.1
  Bottom Layer w10: R65.1@590,1766.5 J33.2@590,1855 U11.2@590,1948.58 ; R65.1@590.5,1766 R59.2@647.5,1766
NetJ33_3: J33.3 R67.1 | length 149.2
  Bottom Layer w10: R67.1@361.5,1905 440,1905 J33.3@490,1855
NetJ34_2: J34.2 R60.2 R66.1 U11.1 | length 249.1
  Bottom Layer w10: U11.1@590,1981.42 J34.2@590,2075 ; J34.2@591.5,2076.5 R66.1@591.5,2175 R60.2@648.5,2175
NetJ34_3: J34.3 R68.1 | length 157.5
  Bottom Layer w10: R68.1@361.5,2005 420,2005 J34.3@490,2075
NetJ35_1: J35.1 R63.2 | length 134.7
  Bottom Layer w10: R63.2@1016.5,1125 1065,1125 1080,1110 J35.1@1145,1110
NetJ35_2: J35.2 R64.2 | length 134.7
  Bottom Layer w10: R64.2@1016.5,995 1065,995 1080,1010 J35.2@1145,1010
NetJ36_2: J36.2 R68.2 | length 74.1
  Bottom Layer w10: J36.2@224.41,2005 R68.2@298.5,2005
NetJ36_3: J36.3 R67.2 | length 74.1
  Bottom Layer w10: J36.3@224.41,1905 R67.2@298.5,1905
NetJ37_1: J37.1 TP30.1 U3.D7 | length 2004.8
  Top Layer w8: U3.D7@4877.24,1807.87 4902.13,1807.87 4924,1786 5004,1786 v3(5017,1799)
  Signal Layer 2 w10: TP30.1@3655,2610 3750,2610 3760,2620 J37.1@3825,2620
  Signal Layer 3 w10: J37.1@3825,2620 3825,2570 3885,2510 4335,2510 4435,2410 4570,2410 5040,1940 5040,1830 5017,1807 v3(5017,1799)
NetJ37_3: J37.3 TP66.1 U1.D7 | length 2258.6
  Top Layer w8: U1.D7@4877.24,2927.87 4912.87,2927.87 4926,2941 4963,2941 4984,2920 5160,2920
  Top Layer w10: 5160,2920 5200,2960 5375,2960 TP66.1@5440,2895
  Signal Layer 3 w8: J37.3@4025,2620 4060,2585 4070,2575 4405,2575 4492,2488 4778,2488 5075,2785 5330,2785 TP66.1@5440,2895
NetJ38_2: J38.2 TP31.1 U3.E7 | length 2243
  Top Layer w8: U3.E7@4877.24,1792.13 4891.87,1792.13 4916,1768 5022,1768 5043,1789 v3(5043,1799)
  Signal Layer 3 w10: TP31.1@3655,2780 3710,2835 3870,2835 J38.2@3925,2780 3975,2730 3975,2595 4025,2545 4370,2545 4465,2450 4575,2450 5070,1955 5070,1826 v3(5043,1799)
NetJ39_2: J39.2 TP67.1 U1.E7 | length 1912.8
  Top Layer w8: U1.E7@4877.24,2912.13 4918.13,2912.13 4933,2927 4953,2927 4985,2895 ; TP67.1@5245,2895 TP67.1@5250,2900
  Top Layer w10: 4985,2895 TP67.1@5245,2895
  Signal Layer 3 w10: J39.2@3980,2950 4305,2625 4875,2625 5070,2820 5170,2820 TP67.1@5250,2900
NetJ41_1: J41.1 R57.1 R58.1 | length 527.7
  Bottom Layer w10: R58.1@830,2170 845,2170 975,2040 J41.1@975,1967 975,1895 R57.1@845,1765
NetJ42_2: J42.2 R26.2 | length 414.5
  Top Layer w10: R26.2@4990.69,1820 5095,1820 5145,1770 5175,1770 5200,1795 5302,1795 J42.2@5353,1846
NetJ43_2: J43.2 R1.2 | length 608.3
  Top Layer w10: R1.2@5049.69,2945 5135,2945 5175,2985 5450,2985 5492,2943 J43.2@5624,2943
NetR9_1: R9.1 TP11.1 U2.10 | length 900.2
  Top Layer w10: TP11.1@4070,505 4175,610 4740,610 4815,685 4820,685 v3(4825,690) 4830.31,690 R9.1@4845,704.68 4849.84,709.53 U2.10@4849.84,745.2
NetR13_2: R13.2 U2.21 | length 57.6
  Top Layer w9: U2.21@4849.84,894.8 4849.84,909.84 4855,915 R13.2@4855,950.31
NetR15_1: R15.1 U1.A7 | length 110.6
  Top Layer w10: U1.A7@4877.24,2975.12 4885.12,2975.12 4915,3005 4915,3040 R15.1@4897,3058
NetR16_1: R16.1 U1.B7 | length 69.2
  Top Layer w10: U1.B7@4877.24,2959.37 4894.37,2959.37 4910,2975 R16.1@4940,2975
NetR17_2: R17.2 R18.2 R19.2 TP14.1 U2.11 | length 574.9
  Top Layer w8: R19.2@4869.53,639.84 U2.11@4869.53,745.2
  Top Layer w10: TP14.1@4505,500 4810,500 4864.69,554.69 R18.2@4864.69,575 R17.2@4864.69,605 R19.2@4864.69,635 R19.2@4869.53,639.84
NetR33_1: R33.1 U3.B7 | length 84.2
  Top Layer w8: U3.B7@4877.24,1839.37 4884.37,1839.37 4924,1879 R33.1@4945,1879
NetR44_1: R44.1 R45.2 U7.9 | length 149.6
  Bottom Layer w10: U7.9@378.43,1146.53 378.43,1203.43 395,1220 395,1257.56 R44.1@417.44,1280
NetR49_1: R49.1 U7.3 | length 169
  Bottom Layer w10: U7.3@431.57,1107.16 492.84,1107.16 510,1090 R49.1@593.5,1090
NetR50_2: R50.2 R55.1 U10.1 | length 108.6
  Bottom Layer w10: U10.1@372.36,2496.22 372.36,2445.87 R55.1@371.5,2445 R50.2@428.5,2445
NetR51_2: R51.2 R56.1 U10.2 | length 108.6
  Bottom Layer w10: U10.2@372.36,2523.78 372.36,2574.13 R56.1@371.5,2575 R51.2@428.5,2575
NetR61_2: R61.2 R63.1 U12.2 | length 108.6
  Bottom Layer w10: U12.2@897.36,1073.78 896.5,1074.65 R61.2@896.5,1125 R63.1@953.5,1125
NetR62_2: R62.2 R64.1 U12.1 | length 108.6
  Bottom Layer w10: U12.1@897.36,1046.22 897.36,995.87 R62.2@896.5,995 R64.1@953.5,995
NetR65_2: R65.2 TP64.1 | length 172.5
  Bottom Layer w10: TP64.1@355,1765 R65.2@527.5,1765
NetR66_2: R66.2 TP65.1 | length 175
  Bottom Layer w10: TP65.1@355,2175 R66.2@530,2175
NetR69_1: R69.1 TP40.1 | length 176.3
  Bottom Layer w10: R69.1@851.5,1350 851.5,1436.5 TP40.1@915,1500
NetR70_1: R70.1 TP68.1 | length 342.6
  Bottom Layer w10: R70.1@951.5,1255 1010,1255 1020,1245 TP68.1@1290,1245
NetTP47_1: TP47.1 U5.36 | length 586.8
  Top Layer w10: TP47.1@930,2880 1005,2880 1095,2790 1255,2790 1300.16,2744.84 U5.36@1300.16,2584.17
NetTP48_1: TP48.1 U5.26 | length 567.4
  Top Layer w10: U5.26@1424.17,2479.84 1584.84,2479.84 1760,2655 TP48.1@1919,2655
NetTP50_1: TP50.1 U5.35 | length 458.4
  Top Layer w10: TP50.1@1090,2880 1155,2815 1270,2815 1319.84,2765.16 U5.35@1319.84,2584.17
NetTP51_1: TP51.1 U5.25 | length 490
  Top Layer w10: U5.25@1424.17,2460.16 1584.84,2460.16 1595,2450 TP51.1@1910,2450
NetTP52_1: TP52.1 U5.34 | length 332.9
  Top Layer w10: TP52.1@1250,2880 1339.53,2790.47 U5.34@1339.53,2584.17
NetTP53_1: TP53.1 U5.12 | length 340.2
  Top Layer w10: TP53.1@1185,2050 1185,2290 1207,2312 1226,2312 1241.1,2327.1 U5.12@1241.1,2355.83
NetTP54_1: TP54.1 U5.27 | length 623.4
  Top Layer w10: U5.27@1424.17,2499.53 1509.53,2499.53 TP54.1@1890,2880
NetTP55_1: TP55.1 U5.28 | length 500.4
  Top Layer w10: U5.28@1424.17,2519.21 1446.21,2519.21 1730,2803 TP55.1@1730,2880
NetTP56_1: TP56.1 U5.18 | length 322.7
  Top Layer w10: U5.18@1359.21,2355.83 1359.21,2328.79 1380,2308 1380,2140 1360,2120 TP56.1@1360,2050
NetTP57_1: TP57.1 U5.40 | length 649.8
  Top Layer w10: TP57.1@770,2880 845,2805 1045,2805 1085,2765 1170,2765 1210,2725 1210,2615 1221.42,2603.58 U5.40@1221.42,2584.17
NetTP58_1: TP58.1 U5.19 | length 372.6
  Top Layer w10: U5.19@1378.9,2355.83 1378.9,2337.1 1540,2176 TP58.1@1540,2050
NetTP59_1: TP59.1 U5.3 | length 895.3
  Top Layer w10: TP59.1@450,2880 690,2640 1025,2640 1145.79,2519.21 U5.3@1195.83,2519.21
NetTP60_1: TP60.1 U5.20 | length 450.5
  Top Layer w10: U5.20@1398.58,2355.83 1410.17,2355.83 TP60.1@1720.5,2045.5
NetTP61_1: TP61.1 U5.2 | length 727.1
  Top Layer w10: TP61.1@610,2880 826,2664 1036,2664 1161.1,2538.9 U5.2@1195.83,2538.9
NetTP62_1: TP62.1 U5.21 | length 630.5
  Top Layer w10: U5.21@1424.17,2381.42 1424.17,2368.83 1558,2235 1720,2235 1905,2050 TP62.1@1910,2050
NetTP63_1: TP63.1 U5.22 | length 542.2
  Top Layer w10: U5.22@1424.17,2401.1 1440.9,2401.1 1577,2265 TP63.1@1910,2265
OTG_SCHG: J2.1 R4.1 U2.8 U5.16 | length 5664.8
  Top Layer w8: U5.16@1319.84,2355.83 1319.84,2329.16 1324,2325 1324,2311 1335,2300 v3(1335,2229) ; v3(4780,720) 4800,720 4810.47,730.47 U2.8@4810.47,745.2
  Signal Layer 2 w10: J2.1@2185,145 2185,105 2225,65 4190,65 4805,680 4805,695 v3(4780,720)
  Signal Layer 3 w10: v3(1335,2229) 1335,2190 1295,2150 1295,1990 1370,1915 1370,1545 2185,730 v1(2185,299)
  Bottom Layer w10: J2.1@2185,145 R4.1@2185,330.32
QON_SCHG: U2.12 U5.17 | length 4273.5
  Top Layer w8: U5.17@1339.53,2355.83 1339.53,2322.47 1358,2304 v3(1358,2294)
  Top Layer w9: v3@4889.21,723.21 U2.12@4889.21,745.2
  Top Layer w10: v3(4889,723) v3@4889.21,723.21
  Signal Layer 3 w8: v3(1358,2294) 1402,2294 1511,2185 1916,2185 3237,864 4300,864 4355,809 4632,809 4697,744 4868,744 v3(4889,723)
RX_MCU: R53.2 R62.1 U5.24 | length 2152.6
  Top Layer w10: U5.24@1424.17,2440.47 1514.53,2440.47 v3@1520,2435
  Signal Layer 2 w10: v1(830,1030) 865,1030 1240,1405 1485,1405 1655,1575 1655,2305 v3(1525,2435)
  Bottom Layer w10: R53.2@776.5,1030 v1(830,1030) 830,998.5 R62.1@833.5,995
SCL: R58.2 R60.1 U1.F7 U2.5 U3.F7 U4.B3 | length 8129.2
  Top Layer w8: U4.B3@820.75,1260 v2(845,1260)
  Top Layer w10: v2(4745,790) 4745.47,790.47 U2.5@4765.2,790.47
  Signal Layer 2 w9: 4846,1680.72 4846,1771 ; 4846,2890 4846,2859 4865,2840
  Signal Layer 2 w10: v2(845,1260) 845,1710 760,1795 660,1795 640,1815 640,2120 695,2175 861,2175 1195,2509 1195,2613.72 1326.28,2745 2950,2745 3205,3000 4830,3000 4854,2976 4869,2976 4880,2965 4880,2899.13 v2(4877.24,2896.38) 4852.38,2896.38 4846,2890 ; v2(4745,790) 4745,1010 4790,1055 4790,1445 4865,1520 4865,1661.72 4846,1680.72 ; 4846,1771 4851.38,1776.38 v2(4877.24,1776.38) 4877.24,2037.76 4815,2100 4815,2610 4865,2660 4865,2840
  Bottom Layer w10: R60.1@711.5,2175 R58.2@768.5,2175
  other v1: 745,2175
SCL_MCU: J34.1 J44.7 U5.11 | length 1418.3
  Top Layer w10: v3(1210,2335) 1221.42,2346.42 U5.11@1221.42,2355.83
  Signal Layer 2 w10: J34.1@690,2075 690,2020 1015,1695 J44.7@1220,1695 1220,1765 1245,1790 1245,2090 1200,2135 1200,2325 v3(1210,2335)
SDA: R57.2 R59.1 U1.G7 U2.6 U3.G7 U4.C3 | length 8341.3
  Top Layer w8: U4.C3@820.75,1244.25 v2@834.25,1244.25
  Top Layer w10: v2(4745,770) 4745.79,770.79 U2.6@4765.2,770.79
  Signal Layer 2 w10: v2(835,1245) 825,1255 825,1685 744.25,1765.75 611.25,1765.75 540,1837 540,2110 635,2205 848,2205 1170,2527 1170,2630 1315,2775 2940,2775 3195,3030 4825,3030 4860,2995 4879,2995 4900,2974 4900,2890 4890.63,2880.63 v2(4877.24,2880.63) 4877.24,2867.76 4890,2855 4890,2650 4840,2600 4840,2111 4900,2051 4900,1770 4890.63,1760.63 v2(4877.24,1760.63) 4877.24,1682.76 4890,1670 4890,1505 4815,1430 4815,1030 4765,980 4765,780 4755,770 v2(4745,770)
  Bottom Layer w10: R59.1@710.5,1766 R57.2@767.5,1766
  other v1: 745,1765
SDA_MCU: J33.1 J44.8 U5.10 | length 1486
  Top Layer w10: U5.10@1195.83,2381.42 1199.58,2381.42 1200,2381 v3@1200,2370
  Signal Layer 2 w10: J33.1@690,1855 785,1855 1045,1595 1200,1595 1270,1665 1270,2175 1280,2185 1280,2275 1235,2320 1235,2350 1220,2365 v3(1195,2365)
SRN: J20.1 NT6.2 U1.B6 | length 2809.1
  Top Layer w10: NT6.2@6025,2010 v3(6025,2035)
  Signal Layer 3 w10: v2(4861.5,2959.37) 4962.37,2959.37 4970,2967 5142,2967 5185,3010 5835,3010 6020,2825 6240,2825 6275,2860 6360,2860 6390,2830 6390,2790 6365,2765 6295,2765 6280,2750 6280,2670 6390,2560 6390,2365 6335,2310 6245,2310 6025,2090 v3(6025,2035)
SRP: J21.1 NT5.2 U1.A6 | length 2919.3
  Top Layer w8: U1.A6@4861.5,2975.12 4861.5,2981.5 4875,2995 4880,2995 4894,3009 v3(4894,3031)
  Top Layer w10: NT5.2@6050,2010 v3(6050,2035)
  Signal Layer 3 w10: v3(4894,3031) 4927,2998 4951,2998 4962,3009 4979,3009 4990,3020 5114,3020 5149,3055 6305,3055 6410,2950 6410,2735 6386,2711 J21.1@6340,2711 6340,2655 6410,2585 6410,2290 6385,2265 6255,2265 6050,2060 v3(6050,2035)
